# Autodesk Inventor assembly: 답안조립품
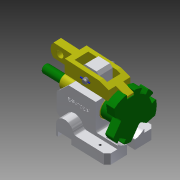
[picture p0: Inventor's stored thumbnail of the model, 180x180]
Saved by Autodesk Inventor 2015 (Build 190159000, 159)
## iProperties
Created: 2016-11
Part Number: 답안조립품
Document SubType Name: Assembly
Designer: Administrator
Author: Administrator
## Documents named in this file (8)
- C:\Users\Administrator\Desktop\461107V1017\답안조립품.iam
- C:\Users\Administrator\Desktop\461107V1017\본체.ipt
- C:\Users\Administrator\Desktop\461107V1017\부시.ipt
- C:\Users\Administrator\Desktop\461107V1017\분할축.ipt
- C:\Users\Administrator\Desktop\461107V1017\분할대.ipt
- C:\Users\Administrator\Desktop\461107V1017\클레비스핀.ipt
- C:\Users\Administrator\Desktop\461107V1017\와셔.ipt
- C:\Users\Administrator\Desktop\461107V1017\원통형핀.ipt
